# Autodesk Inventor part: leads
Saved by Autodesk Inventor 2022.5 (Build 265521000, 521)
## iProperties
Created: 2024-12
Part Number: leads
Material: Generic
Document SubType Name: Modeling
Designer: AdminForWorker
Density: 1 g/cm^3
Appearance: Default
Title: leads
Author: AdminForWorker
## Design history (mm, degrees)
feature "Body1"
feature "Body2"
feature "Body3"
feature "Body4"
feature "Body5"
feature "Body6"
feature "Body7"
feature "Body8"
feature "Body9"
body "Solid1"
body "Solid2"
body "Solid3"
body "Solid4"
body "Solid5"
body "Solid6"
body "Solid7"
body "Solid8"
body "Solid9"
